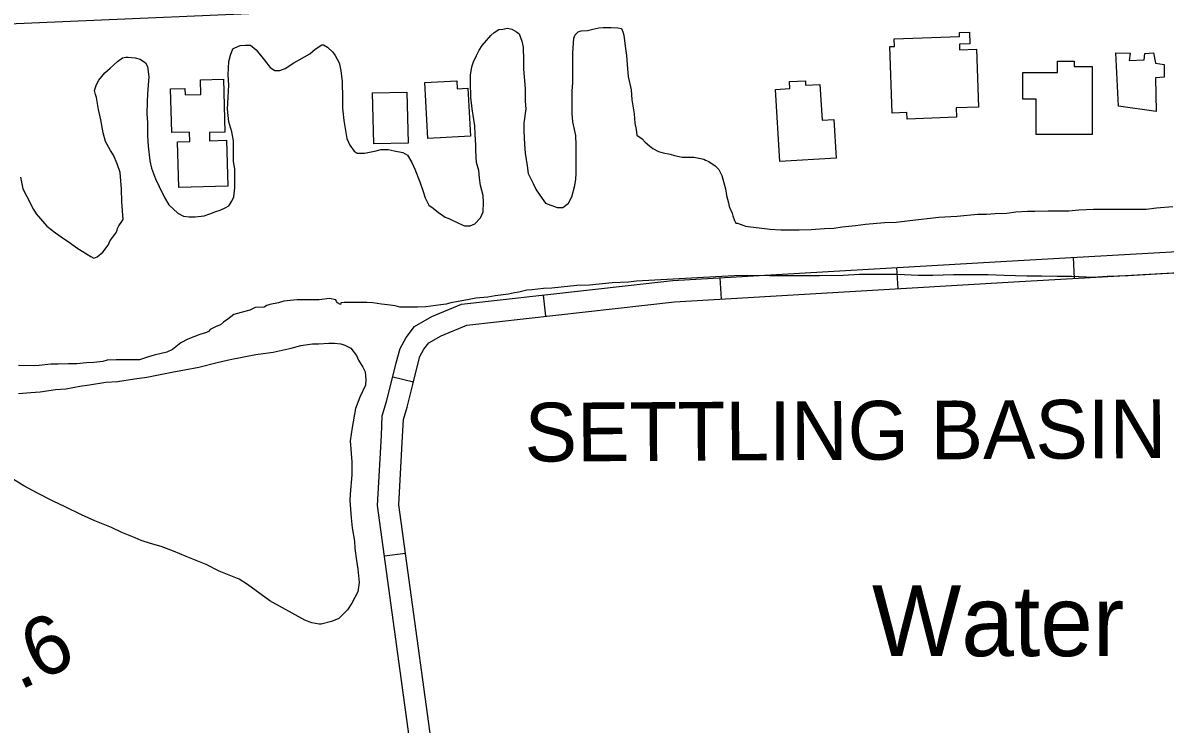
# Model space of a CAD drawing. Extents: x 3313442 to 3351311, y 721974 to 747360.
# Drawn here: x 3324830 to 3326444, y 733684 to 734675 of the extents above; entities that cross this region are included whole.
import ezdxf

# ---------------------------------------------------------------- set-up
doc = ezdxf.new("R2010")
doc.units = 0
for name, color, linetype in [('V-BLDG-IDEN', 7, 'Continuous'), ('V-BLDG-OTLN', 7, 'Continuous'), ('V-RIVR-IDEN', 7, 'Continuous'), ('V-RIVR-RANG-IDEN', 7, 'Continuous'), ('V-ROAD-CNTR', 7, 'Continuous'), ('V-SITE-VEGE', 7, 'Continuous')]:
    doc.layers.add(name, color=color, linetype=linetype)

msp = doc.modelspace()

# ---------------------------------------------------------------- linework, layer by layer
at = {"layer": 'V-BLDG-OTLN'}
for points in [[(3326058, 734547.4), (3326054.8, 734641.4), (3326061.3, 734641.6), (3326060.9, 734652.2), (3326153.1, 734655.4), (3326152.9, 734661.1), (3326167, 734661.5), (3326167.5, 734645.2), (3326153, 734644.7), (3326153.3, 734636.9), (3326177.3, 734637.8), (3326180.1, 734555.7), (3326148.3, 734554.6), (3326148.7, 734541.4), (3326079, 734539), (3326078.7, 734548.1)], [(3326261.3, 734517.1), (3326261.4, 734566.9), (3326242.5, 734566.9), (3326242.6, 734604.8), (3326291.5, 734604.8), (3326291.5, 734620.5), (3326315, 734620.5), (3326315, 734613.2), (3326340.7, 734613.2), (3326340.5, 734517)], [(3326377.9, 734557.1), (3326374, 734632.3), (3326394.4, 734632), (3326392.6, 734621.8), (3326414.1, 734622.4), (3326414.9, 734631.4), (3326427.4, 734632.3), (3326429.9, 734617.9), (3326442.3, 734616.2), (3326442.4, 734597.9), (3326430, 734597.4), (3326431, 734549.4)], [(3325050, 734442.3), (3325048.3, 734506.8), (3325065.8, 734507.3), (3325065.4, 734520.5), (3325040.1, 734519.8), (3325038.5, 734581.6), (3325058.7, 734582.1), (3325059, 734573.2), (3325081.3, 734573.8), (3325080.8, 734594.2), (3325113.3, 734595.1), (3325115.3, 734520.4), (3325093.3, 734519.8), (3325093.6, 734508.4), (3325117.5, 734509.1), (3325119.3, 734444.1)], [(3325401.9, 734511.6), (3325397.8, 734590.8), (3325442.9, 734593.1), (3325443.5, 734581.6), (3325458.5, 734582.4), (3325462, 734514.7)], [(3325899.4, 734479), (3325893.3, 734580.7), (3325913.2, 734581.9), (3325912.7, 734591.8), (3325935.3, 734593.1), (3325935.7, 734586.7), (3325955.9, 734587.9), (3325958.9, 734537.4), (3325975.7, 734538.4), (3325978.9, 734483.7)], [(3325325.6, 734503.8), (3325323.9, 734575.9), (3325372.4, 734577.1), (3325374.1, 734505)]]:
    msp.add_lwpolyline(points, close=True, dxfattribs=at)
at = {"layer": 'V-ROAD-CNTR'}
for p, q in [((3326064, 734329.4), (3326065.8, 734299.4)), ((3326313.7, 734343.8), (3326315.3, 734313.8)), ((3325814.5, 734314.8), (3325816.2, 734284.8)), ((3325564.9, 734290.3), (3325568.3, 734260.5)), ((3325352.4, 734174.7), (3325381.5, 734167.6)), ((3325340.7, 733921.9), (3325370.4, 733926))]:
    msp.add_line(p, q, dxfattribs=at)
for points in [[(3327445.3, 734781.4), (3325663.8, 734710.1), (3324415, 734655.9)], [(3325391.5, 733550.2), (3325330.9, 733993.1), (3325336.3, 734092), (3325337.5, 734120), (3325343.6, 734140), (3325351.6, 734171.5), (3325357.3, 734194.6), (3325362.8, 734214.9), (3325371.2, 734230.4), (3325383.2, 734245.8), (3325407.6, 734260), (3325449.3, 734277.3), (3325748.1, 734310.9), (3326236.1, 734339.4), (3326819.4, 734372.2)], [(3325420.7, 733558), (3325361, 733994.3), (3325366.2, 734090.5), (3325367.3, 734114.8), (3325372.5, 734131.9), (3325380.7, 734164.2), (3325386.3, 734187.1), (3325390.8, 734203.7), (3325396.3, 734213.9), (3325403.3, 734222.8), (3325420.9, 734233), (3325456.8, 734247.9), (3325750.6, 734281), (3326237.8, 734309.5), (3326820.9, 734342.3)]]:
    msp.add_lwpolyline(points, dxfattribs=at)
at = {"layer": 'V-SITE-VEGE'}
for points in [[(3325312.3, 734491), (3325328.7, 734494), (3325335.4, 734495.9), (3325345.8, 734495.8), (3325354.3, 734494), (3325366.5, 734491.6), (3325373.1, 734487.9), (3325379.2, 734477.6), (3325383.5, 734468.4), (3325390.7, 734450.2), (3325395, 734438), (3325398, 734427.6), (3325403.5, 734417.3), (3325409.6, 734413), (3325416.8, 734406.9), (3325426.6, 734400.2), (3325431.4, 734398.4), (3325445.4, 734391.7), (3325453.9, 734388), (3325461.8, 734388), (3325468.5, 734391.1), (3325476.5, 734399.6), (3325480.1, 734408.1), (3325480.7, 734420.9), (3325480.1, 734431.2), (3325476.5, 734445.2), (3325474.7, 734455.5), (3325474.1, 734466.5), (3325470.5, 734477.4), (3325469.9, 734493.9), (3325469.9, 734502.4), (3325468.7, 734517), (3325468.1, 734529.2), (3325464.5, 734553.5), (3325462.7, 734569.9), (3325462.1, 734590.6), (3325462.1, 734601), (3325463.9, 734612.5), (3325466.4, 734619.8), (3325470.7, 734628.9), (3325474.3, 734636.2), (3325478.6, 734642.9), (3325490.8, 734656.9), (3325495.6, 734661.1), (3325502.3, 734665.4), (3325507.8, 734666), (3325514.5, 734667.2), (3325520.6, 734666), (3325527.3, 734662.3), (3325530.9, 734659.3), (3325534.6, 734648.9), (3325536.4, 734640.4), (3325537, 734622.2), (3325536.9, 734609.4), (3325539.3, 734582), (3325539.3, 734564.4), (3325540.5, 734553.4), (3325537.5, 734533.3), (3325537.4, 734521.8), (3325538.6, 734503.5), (3325539.2, 734490.7), (3325542.3, 734473.1), (3325543.5, 734462.1), (3325550.7, 734448.1), (3325555, 734439), (3325563.5, 734426.8), (3325568.3, 734420.1), (3325584.8, 734414), (3325592.7, 734414), (3325600.6, 734420.1), (3325605.5, 734429.2), (3325609.7, 734445), (3325611, 734454.2), (3325611.6, 734462.1), (3325611.6, 734502.2), (3325611.1, 734515.6), (3325606.8, 734535.1), (3325605.6, 734546.6), (3325605.6, 734578.3), (3325606.9, 734590.4), (3325606.9, 734631.8), (3325608.2, 734653.1), (3325610, 734658), (3325614.3, 734662.2), (3325618.5, 734663.4), (3325627.7, 734664), (3325635, 734665.8), (3325643.5, 734667.7), (3325649.6, 734668.3), (3325661.1, 734668.2), (3325670.2, 734667.6), (3325675.7, 734667), (3325677.5, 734662.1), (3325678.8, 734657.3), (3325680.6, 734642.1), (3325682.4, 734628.7), (3325684.2, 734609.8), (3325684.8, 734598.9), (3325689, 734580), (3325690.2, 734566), (3325693.2, 734546.5)], [(3324942.9, 734350.9), (3324950.2, 734360.7), (3324953.2, 734367.3), (3324961.1, 734377.7), (3324963, 734381.9), (3324963.6, 734384.4), (3324965.4, 734388), (3324969.7, 734394.1), (3324971.5, 734397.1), (3324969.7, 734422.1), (3324969.1, 734439.7), (3324967.3, 734463.4), (3324963.1, 734475.6), (3324957.6, 734487.8), (3324953.4, 734494.5), (3324946.7, 734507.3), (3324943.1, 734519.4), (3324940, 734537.7), (3324936.4, 734552.3), (3324934, 734569.3), (3324932.2, 734573.6), (3324931, 734579.1), (3324934, 734587.6), (3324937.1, 734593.7), (3324945.6, 734604), (3324952.9, 734610.7), (3324963.3, 734620.4), (3324970.6, 734625.3), (3324975.4, 734626.5), (3324978.5, 734626.5), (3324988.2, 734625.2), (3324995.5, 734623.4), (3325002.8, 734618.5), (3325005.8, 734613.1), (3325007.6, 734598.5), (3325007, 734586.9), (3325005.8, 734574.7), (3325005.2, 734563.2), (3325005.1, 734546.1), (3325005.7, 734534), (3325005.7, 734515.1), (3325006.9, 734500.5), (3325009.3, 734479.8), (3325011.7, 734469.5), (3325017.2, 734454.3), (3325022.1, 734443.9), (3325029.9, 734428.1), (3325036, 734417.7), (3325048.8, 734406.2), (3325056.7, 734401.9), (3325064.6, 734400.7), (3325073.1, 734400.7), (3325085.9, 734402.5), (3325093.8, 734404.9), (3325102.3, 734408.5), (3325108.4, 734410.4), (3325115.7, 734413.4), (3325120.6, 734416.4), (3325124.8, 734423.1), (3325127.9, 734429.2), (3325129.1, 734442), (3325129.2, 734468.7), (3325127.4, 734479.1), (3325127.4, 734508.3), (3325125, 734521.1), (3325120.7, 734535.1), (3325118.9, 734552.7), (3325120.8, 734586.8), (3325119.6, 734601.4), (3325120.8, 734620.2), (3325123.3, 734629.3), (3325126.3, 734637.9), (3325129.4, 734639.7), (3325136.7, 734642.7), (3325144, 734643.3), (3325151.3, 734643.3), (3325159.2, 734636.6), (3325171.3, 734622), (3325179.2, 734611.6), (3325185.9, 734607.4), (3325192.6, 734607.4), (3325200.5, 734610.4), (3325212.7, 734618.3), (3325235.2, 734631), (3325242.5, 734637.7), (3325252.3, 734643.8), (3325254.7, 734643.8), (3325260.2, 734640.7), (3325267.5, 734633.4), (3325271.1, 734628.6), (3325276.6, 734618.2), (3325279, 734607.3), (3325280.8, 734591.4), (3325281.4, 734568.3), (3325281.4, 734554.3), (3325283.2, 734536.7), (3325287.4, 734511.7), (3325291.6, 734502), (3325297.7, 734493.5), (3325302, 734491), (3325312.3, 734491)], [(3325693.2, 734546.5), (3325694.4, 734533.1), (3325696.2, 734524), (3325697.4, 734516.1), (3325704.7, 734511.2), (3325709, 734506.4), (3325715.1, 734500.9), (3325719.9, 734497.2), (3325727.8, 734493), (3325734.5, 734491.1), (3325744.3, 734489.3), (3325750.3, 734487.4), (3325757, 734486.2), (3325761.3, 734485), (3325777.7, 734485), (3325791.7, 734482.5), (3325794.1, 734480.7), (3325799, 734478.9), (3325808.1, 734472.8), (3325813, 734467.9), (3325817.2, 734459.4), (3325822.7, 734440.5), (3325823.9, 734430.8), (3325826.9, 734420.4), (3325827.5, 734415.6), (3325831.8, 734405.8), (3325833, 734402.2), (3325835.4, 734395.5), (3325837.2, 734391.8), (3325839.6, 734391.8), (3325848.2, 734388.8), (3325850.6, 734387.6), (3325885.3, 734383.3), (3325900.5, 734382.6), (3325926.6, 734382.6), (3325943.7, 734383.2), (3325962.5, 734384.4), (3325975.3, 734385), (3325987.5, 734386.8), (3326006.3, 734388.6), (3326020.3, 734390.4), (3326047.1, 734392.8), (3326063.5, 734393.4), (3326083, 734395.8), (3326123.8, 734400.6), (3326140.8, 734401.2), (3326149.9, 734401.8), (3326178.5, 734404.8), (3326191.3, 734404.8), (3326203.5, 734405.4), (3326219.9, 734406), (3326232.7, 734407.8), (3326249.1, 734409), (3326259.4, 734409), (3326278.3, 734409.5), (3326307.5, 734409.5), (3326321.5, 734410.7), (3326342.2, 734411.9), (3326417, 734411.8), (3326431.6, 734413.6), (3326454.7, 734415.4)], [(3324826.2, 734456.9), (3324829.8, 734440.5), (3324835.3, 734429.5), (3324845, 734411.3), (3324848.6, 734405.2), (3324863.8, 734387.5), (3324876, 734378.4), (3324888.7, 734369.2), (3324895.4, 734365), (3324905.8, 734357.1), (3324913.7, 734352.2), (3324925.8, 734344.9), (3324930.1, 734342.4), (3324934.9, 734344.2), (3324942.9, 734350.9)], [(3326457.7, 734321.1), (3326439.4, 734320.5), (3326391.4, 734317.5), (3326361.5, 734316.4), (3326342.1, 734315.2), (3326311.7, 734316.4), (3326291, 734316.5), (3326269.1, 734317.1), (3326248.4, 734317.1), (3326216.1, 734317.8), (3326193.6, 734319), (3326144.4, 734319.1), (3326115.2, 734317.9), (3326094.5, 734317.9), (3326065.3, 734319.2), (3326011.7, 734319.2), (3325988.6, 734318), (3325955.1, 734317.5), (3325884.6, 734317.6), (3325853.6, 734318.2), (3325834.7, 734317.6), (3325696.6, 734309.9), (3325685.6, 734308.7), (3325662.5, 734307.5), (3325630.3, 734304.5), (3325612.6, 734303.9), (3325590.1, 734301.5), (3325577.3, 734300.3), (3325565.2, 734299.7), (3325549.3, 734297.9), (3325542, 734297.3), (3325530.5, 734294.3), (3325524.4, 734293.7), (3325515.9, 734291.8), (3325497, 734289.4), (3325486.7, 734287.6), (3325469.6, 734285.8), (3325458.1, 734283.4), (3325434.3, 734279.2), (3325427.6, 734277.3), (3325420.3, 734276.7), (3325399, 734273.7), (3325387.5, 734273.1), (3325362.5, 734273.2), (3325355.9, 734275), (3325344.9, 734276.8), (3325336.4, 734277.5), (3325324.2, 734279.3), (3325315.7, 734279.9), (3325283.5, 734279.9), (3325279.2, 734279.3), (3325278.6, 734276.9), (3325274.3, 734279.4), (3325273.1, 734281.2), (3325271.9, 734283.6), (3325262.8, 734285.4), (3325248.2, 734283.6), (3325243.3, 734283.6), (3325229.3, 734283.7), (3325225.1, 734283.7), (3325217.2, 734283.7), (3325212.3, 734283.1), (3325198.3, 734281.9), (3325191, 734279.5), (3325178.8, 734277), (3325174.6, 734275.8), (3325170.9, 734273.4), (3325158.1, 734272.8), (3325150.2, 734269.2), (3325148.4, 734268.6), (3325143.5, 734267.3), (3325127.7, 734263.1), (3325119.2, 734256.4), (3325113.1, 734252.2), (3325108.8, 734248.5), (3325102.7, 734246.1), (3325094.2, 734241.8), (3325091.8, 734238.8), (3325089.3, 734237.6), (3325079.6, 734234.6), (3325062.6, 734227.9), (3325052.8, 734223), (3325041.2, 734213.3), (3325033.3, 734209.7), (3325015.1, 734205.4), (3325007.2, 734203), (3324994.4, 734198.8)], [(3324823.4, 734151.5), (3324841, 734152.7), (3324854.4, 734153.9), (3324875.7, 734156.9), (3324890.3, 734158.1), (3324910.4, 734161.8), (3324923.8, 734163.6), (3324946.9, 734167.2), (3324963.3, 734168.4), (3324987.7, 734172), (3325004.7, 734174.4), (3325040, 734181.7), (3325058.2, 734184.7), (3325078.3, 734188.3), (3325104.5, 734195), (3325122.8, 734199.2), (3325158.7, 734206.5), (3325183.6, 734209.5), (3325208.6, 734215.6), (3325222.6, 734219.2), (3325239, 734221.6), (3325247.5, 734221.6), (3325262.1, 734222.2), (3325270, 734222.2), (3325279.1, 734221.6), (3325284.6, 734219.7), (3325293.1, 734215.5), (3325301, 734205.1), (3325304, 734198.4), (3325310.1, 734188.7), (3325313.2, 734182), (3325314.4, 734171), (3325313.7, 734163.1), (3325305.8, 734146.1), (3325299.7, 734130.3), (3325294.8, 734103.5), (3325292.4, 734084.7), (3325294.7, 734054.8), (3325294.7, 734036.6), (3325292.3, 734009.2), (3325291.6, 734000.1), (3325293.4, 733975.8), (3325295.2, 733961.8), (3325298.3, 733942.9), (3325298.9, 733932.5), (3325301.3, 733915.5), (3325303.1, 733903.3), (3325304.9, 733884.5), (3325303, 733871.1), (3325294.5, 733855.3), (3325288.4, 733845.6), (3325276.2, 733833.4), (3325265.9, 733829.2), (3325251.3, 733825.5), (3325248.2, 733825.5), (3325237.9, 733827.4), (3325228.2, 733831), (3325178.9, 733858.5), (3325147.3, 733881.6), (3325135.2, 733888.9), (3325107.2, 733900.5), (3325088.9, 733909.7), (3325060.4, 733921.3), (3325042.7, 733928.6), (3325025.1, 733935.3), (3325009.9, 733939.6), (3324997.1, 733943.9)], [(3324994.4, 734198.8), (3324961.5, 734198.8), (3324948.8, 734198.2), (3324942.7, 734196.4), (3324929.9, 734195.2), (3324919.6, 734194.6), (3324906.2, 734193.4), (3324894, 734193.4), (3324879.4, 734192.8), (3324869.1, 734192.8), (3324852.6, 734191), (3324845.9, 734190.4), (3324823.4, 734191.1)], [(3324997.1, 733943.9), (3324988.6, 733947.5), (3324969.8, 733954.8), (3324955.2, 733962.2), (3324931.5, 733971.3), (3324912.6, 733979.9), (3324889.5, 733991.4), (3324872.5, 733999.4), (3324849.4, 734011), (3324831.1, 734020.7), (3324806.8, 734036)]]:
    msp.add_lwpolyline(points, dxfattribs=at)

# ---------------------------------------------------------------- texts
at = {"layer": 'V-BLDG-IDEN'}
msp.add_text('SETTLING BASIN', height=83, rotation=0.3179, dxfattribs=at).set_placement((3325538.9, 734055.1))
at = {"layer": 'V-RIVR-IDEN'}
msp.add_text('Water', height=100, dxfattribs=at).set_placement((3326029.4, 733780.4))
at = {"layer": 'V-RIVR-RANG-IDEN'}
msp.add_text('R-233.6', height=83, rotation=25.2753, dxfattribs=at).set_placement((3324551.4, 733602.4))

doc.saveas('drawing.dxf')
